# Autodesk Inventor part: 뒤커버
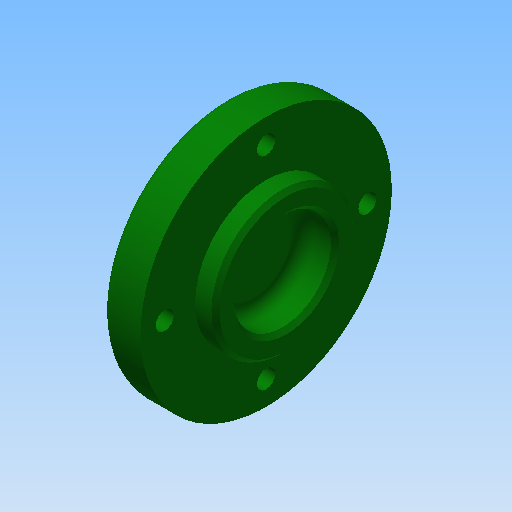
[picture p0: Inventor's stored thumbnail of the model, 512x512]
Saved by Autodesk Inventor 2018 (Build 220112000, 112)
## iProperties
Created: 2015-12
Part Number: 뒤커버
Document SubType Name: Modeling
Designer: mdu
Density: 2.71 g/cm^3
Material: 알루미늄 6061
Mass: 80.8084 g
Surface Area: 93.0376 cm^2
Volume: 29.8186 cm^3
Appearance: 진녹색
Author: mdu
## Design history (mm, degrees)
sketch "스케치1"
  geometry: L1 (-7.5, 0)-(7.5, 0); L2 (-7.5, 0)-(-7.5, 31); L3 (-7.5, 31)-(2.5, 31); L4 (2.5, 31)-(2.5, 17.5); L5 (2.5, 17.5)-(7.5, 17.5); L6 (7.5, 17.5)-(7.5, 0); 2 further points
  constraints: 12 end point, 3 parallel, 1 coincident, 1 horizontal, 1 midpoint, 1 perpendicular
  dimensions: "d0" = 15 distance of L1.start L1.end; "d1" = 62 diameter of L3 L1; "d2" = 35 diameter of L5 L1; "d34" = 10 distance of L2.end L3.end
revolve "회전1" sketch "스케치1" stored, may be unused: angle "d6" = 90 deg
sketch "스케치2" dims "d32" = 50
  geometry: 3 further points
  constraints: 2 vertical alignment, 1 coincident, 2 other
hole "구멍1" sketch "스케치2" at (0, 25) diameter "d8" = 4.5; stored, may be unused: countersink angle "d12" = 90 deg, drill point angle "d14" = 118 deg; dims "d9" = 6, "d10" = 8, "d11" = 4.4, "d13" = 8
hole "구멍2" diameter "d20" = 24; stored, may be unused: countersink angle "d24" = 90 deg, drill point angle "d26" = 0 deg; dims "d18" = 10, "d19" = 10, "d21" = 6, "d22" = 8, "d23" = 4.4, "d25" = 8
fillet "모깎기1" dims "d27" = 3
fillet "모깎기2" dims "d28" = 3
chamfer "모따기1" distance "d29" = 1; stored, may be unused: second distance "d30" = 2, angle "d31" = 45 deg
node "솔리드1"
pattern_circular "원형 패턴1" dims angle "d16" = 360 deg
